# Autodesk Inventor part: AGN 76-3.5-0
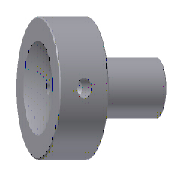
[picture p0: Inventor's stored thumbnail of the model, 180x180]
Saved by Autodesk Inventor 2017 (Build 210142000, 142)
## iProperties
Created: 2016-02
Part Number: AGN 76-3.5-0
Material: DIN 1.2312
Description: Sprue Bushing
Document SubType Name: Modeling
Designer: Sandeep
Standard Revision: 1
Manufacturer: DME
Language: en-US
Size Designation: 76-3.5-0
Categories: <MemberInstance><Categories><Category DisplayName="Mold" InternalName="349578f2-f4d4-4954-8c09-8e99297a61c0" Mnemonic="MOLD"><Category DisplayName="Runners" Int
Density: 7.85 g/cm^3
Appearance: Default
IsCustomPart: 1
Author: Sandeep
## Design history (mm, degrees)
sketch "Sketch1"
  geometry: L1 (0, -27.2)-(0, 23.2) reference; L2 (1.75, 20)-(19, 20); L3 (19, 20)-(19, 0); L4 (19, 0)-(12, 0); L5 (9, -3)-(9, -76); L6 (9, -76)-(4.264, -76); L7 (4.264, -76)-(1.75, 20); A1 r 3 centre (12, -3) between (12, 0) and (9, -3); 2 further points
  constraints: 12 end point, 3 parallel, 2 perpendicular, 2 point on circle, 2 point on line, 2 tangent, 1 centre point
  dimensions: "d0" = 18 diameter of L5 L1 (= D); "d3" = 38 diameter of L3 L1 (= d1); "d6" = 1.5 deg angle of L7 L1 (= 0.5 x Taper); "d7" = 20 distance between parallel lines of L4 L2 (= K_); "d8" = 76 distance between parallel lines of L4 L6 (= L); "d9" = 3 radius of A1 (= R3); "d62" = 3.5 diameter of point (1.75, 20) L1 (= d_); "d63" = 0 distance from line of point (1.75, 20) L2 (computed from Rd)
revolve "Revolution1" sketch "Sketch1" stored, may be unused: angle "d10" = 90 deg
sketch "Sketch2"
  geometry: L1 (0, -32.79)-(0, 56.739) reference; L2 (4.264, -76)-(1.75, 20) reference; L3 (-19, 20)-(19, 20) reference; L4 (0, 50.901)-(0, 19.901); A1 r 15.5 centre (0, 35.401) between (0, 19.901) and (0, 50.901); 2 further points
  constraints: 3 point on circle, 3 point on line, 2 end point, 1 centre point, 1 midpoint
  dimensions: "d64" = 0 distance from line of point (1.75, 20) L3 (computed from Rd); "d67" = 15.5 radius of A1 (= Rk)
revolve "Revolution2" sketch "Sketch2" stored, may be unused: angle "d13" = 90 deg
workplane "Work Plane1"
sketch "Sketch3"
  geometry: 2 further points
  constraints: 1 vertical alignment
  dimensions: "d43" = 10 distance of point (0, -10) point (0, 0) (= 0.5 x K_)
hole "Hole1" sketch "Sketch3" at (0, 0) diameter "d15" = 4 (= pd1); stored, may be unused: countersink angle "d19" = 90 deg, drill point angle "d21" = 118 deg; dims "d16" = 6, "d17" = 4, "d18" = 2, "d20" = 6 (= pl1)
chamfer "Chamfer1" distance "d22" = 0.3; stored, may be unused: second distance "d23" = 2, angle "d24" = 45 deg
sketch "Sketch4"
  geometry: L1 (0, -30.4)-(0, 42.4) reference; L2 (0, 40)-(19.5, 40); L3 (19.5, 40)-(19.5, 0); L4 (9, -76)-(0, -76); L5 (0, -76)-(0, 40); L6 (9, -3)-(9, -76); L7 (12, 0)-(19.5, 0); L8 (12, 0)-(9, -3); 2 further points
  constraints: 14 end point, 4 point on line, 2 horizontal, 2 parallel, 1 perpendicular, 1 vertical
  dimensions: "d56" = 3 distance of L7.start point (9, 0) (= R3_CS); "d57" = 3 distance of L6.start point (9, 0) (= d56); "d58" = 39 diameter of L3 L1 (= d1_CS); "d59" = 40 distance between parallel lines of L7 L2 (= K_CS); "d60" = 18 diameter of L6 L1 (= D_CS); "d61" = 76 distance between parallel lines of L7 L4 (= L_CS)
feature "RevolutionSrf1" sketch "Sketch4" dims angle "d33" = 90 deg
body "Solid1"
body "Srf1"
other parameters: "L" = 76 [user parameter; used in 1 equation term], "d1" = 38 [user parameter; used in 1 equation term], "d_" = 3.5 [user parameter; used in 1 equation term], "D" = 18 [user parameter; used in 1 equation term], "K_" = 20 [user parameter; used in 2 equation terms], "R" = 0 [user parameter], "Taper" = 3 deg [user parameter; used in 1 equation term], "Rd" = 0 [user parameter; used in 2 equation terms], "R3" = 3 [user parameter; used in 1 equation term], "pd1" = 4 [user parameter; used in 1 equation term], "d1_CS" = 39 [user parameter; used in 1 equation term], "K_CS" = 40 [user parameter; used in 1 equation term], "d44" = 0, "d45" = 0, "d46" = 0, "L_CS" = 76 [user parameter; used in 1 equation term], "D_CS" = 18 [user parameter; used in 1 equation term], "pl1" = 6 [user parameter; used in 1 equation term], "R3_CS" = 3 [user parameter; used in 1 equation term], "Rk" = 15.5 [user parameter; used in 1 equation term]
